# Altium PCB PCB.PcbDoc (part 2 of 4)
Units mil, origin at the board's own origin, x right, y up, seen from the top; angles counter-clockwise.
Board outline 6311.26 x 4737.49 mil, 2 copper layers (Top Layer, Bottom Layer); 252 components, 238 nets, 1140 pads, 635 vias.
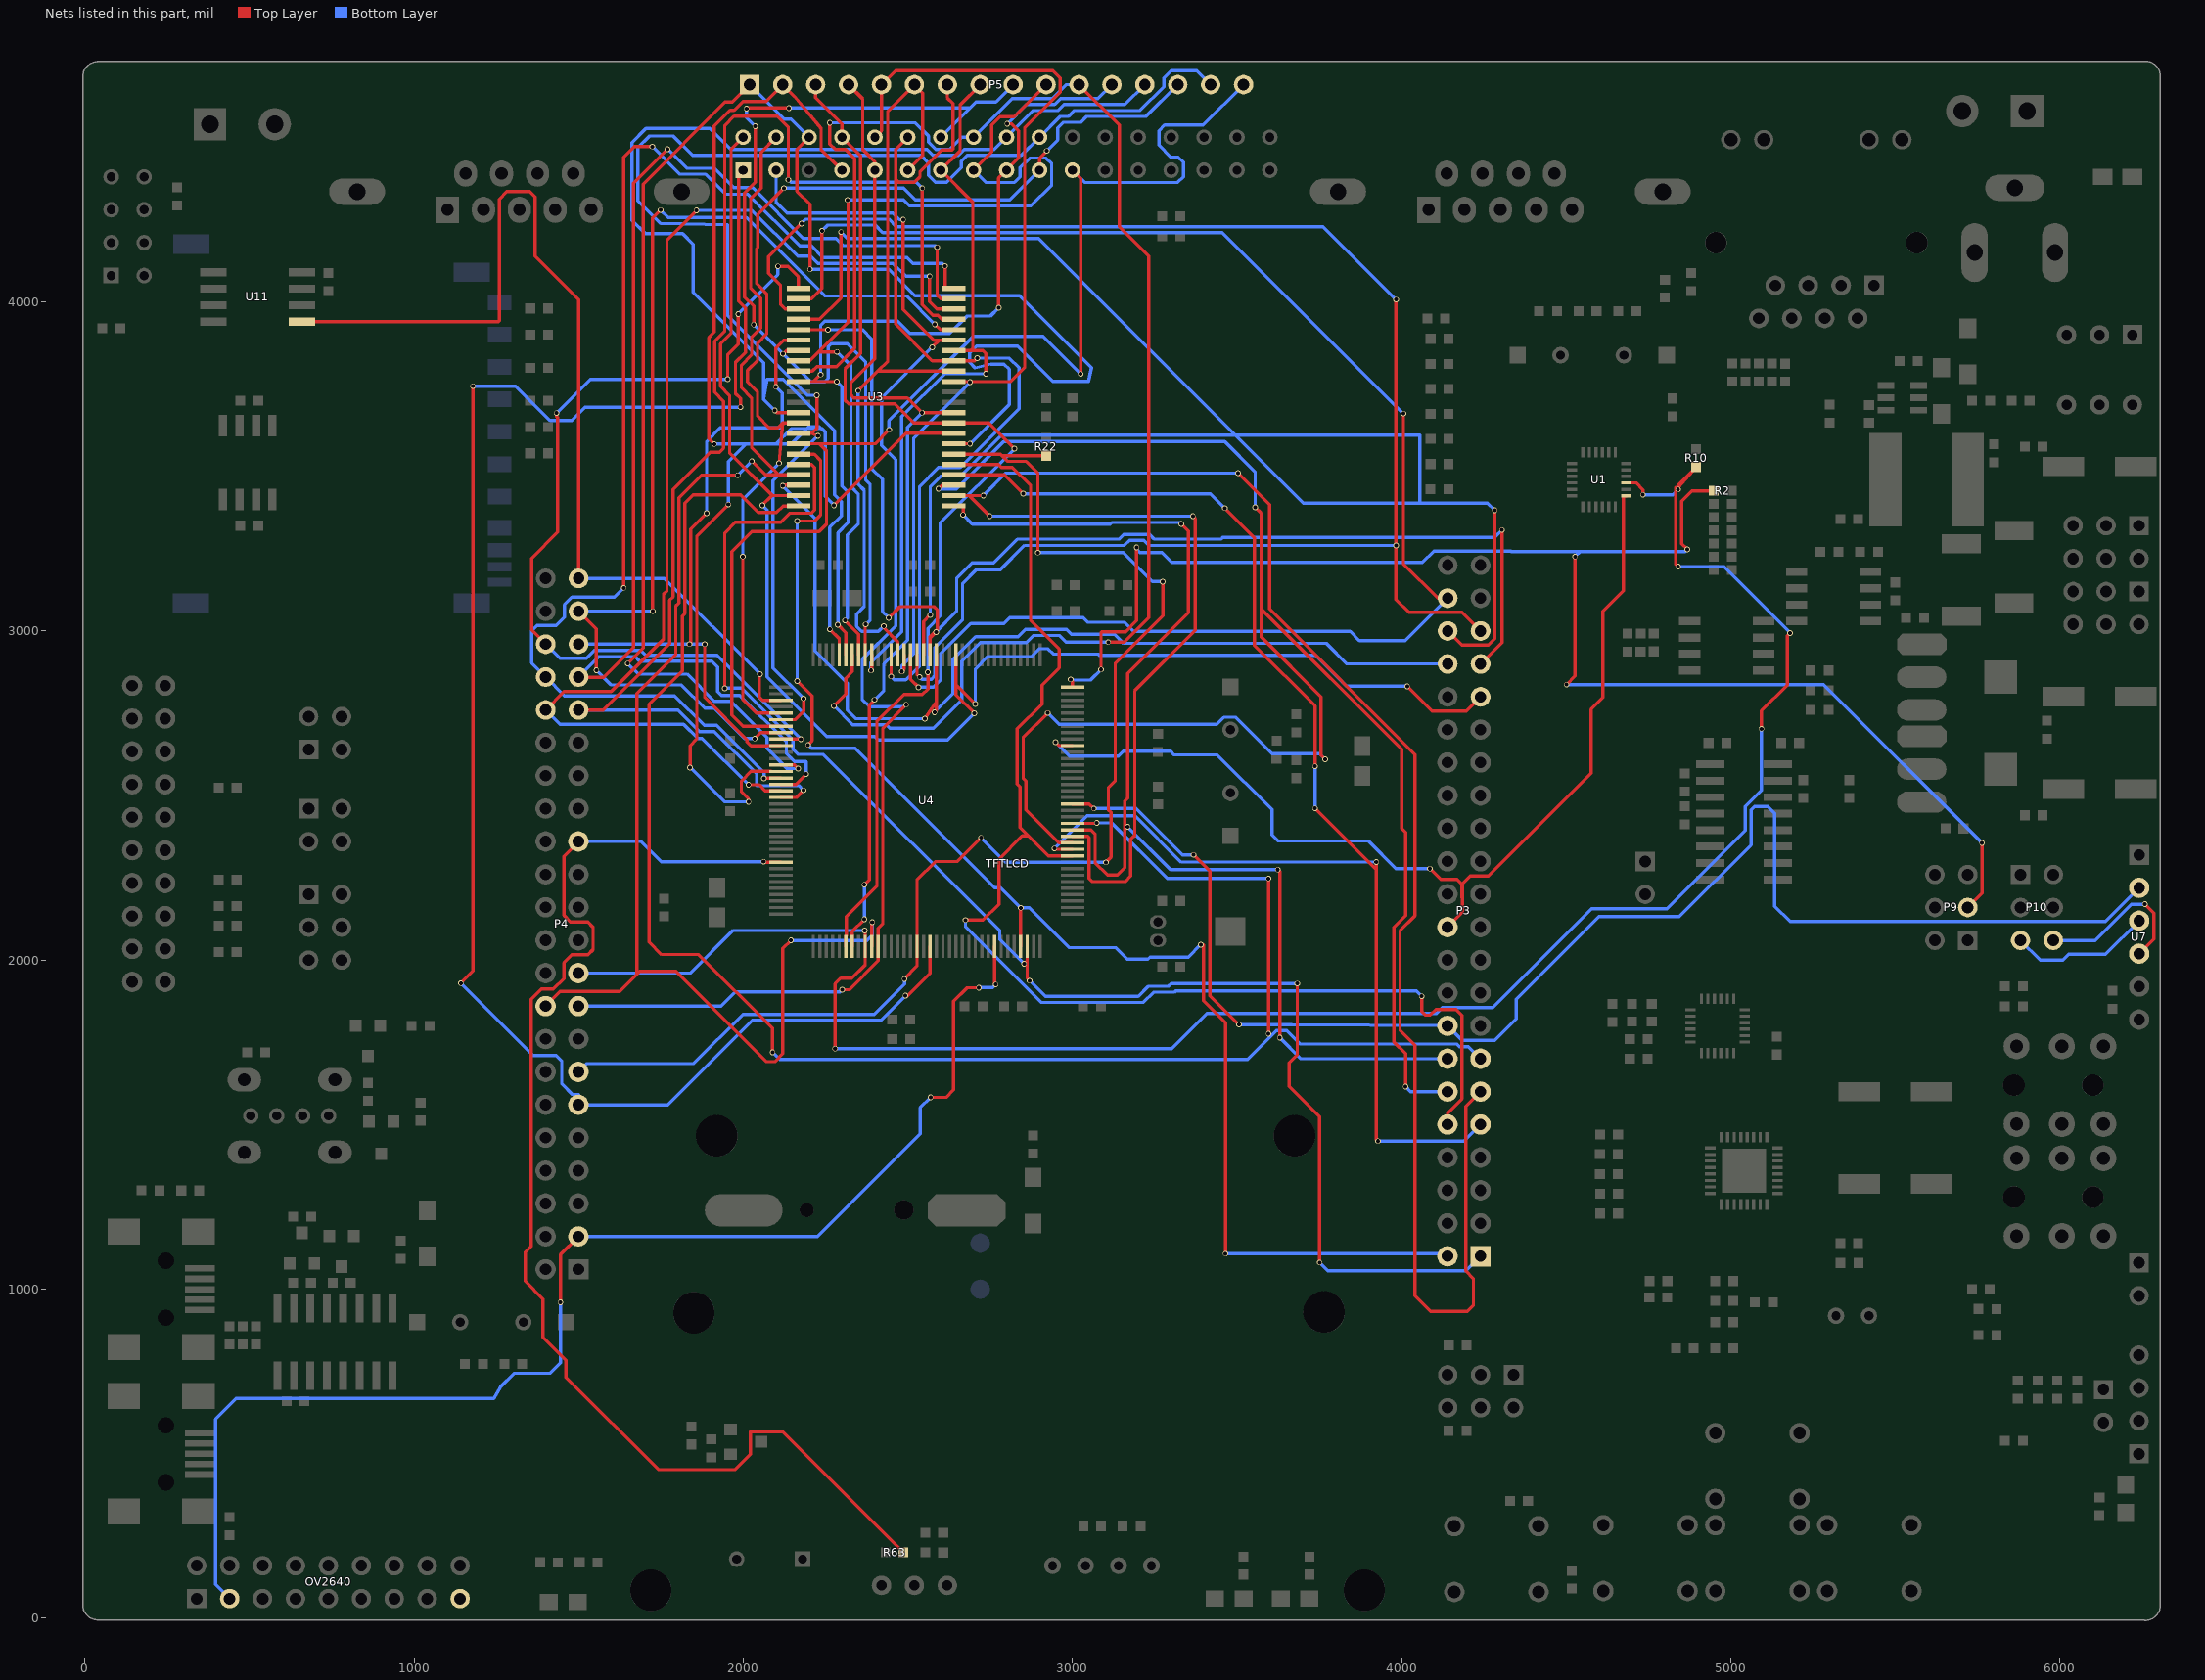
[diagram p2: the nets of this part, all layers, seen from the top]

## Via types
v1: diameter 17, hole 12, Top Layer to Bottom Layer, 622 vias
v2: diameter 25, hole 15, Top Layer to Bottom Layer, 9 vias
v3: diameter 275.59, hole 129.92, Top Layer to Bottom Layer, 4 vias

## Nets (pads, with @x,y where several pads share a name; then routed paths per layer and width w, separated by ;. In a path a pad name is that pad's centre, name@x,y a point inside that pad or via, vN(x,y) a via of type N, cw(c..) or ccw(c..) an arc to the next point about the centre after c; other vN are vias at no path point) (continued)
DCMI_VSYNC: OV2640.3 P4.3 U4.137 | length 3998.9
  Top Layer w10: v1(1445,960) 1445,1105.85 P4.3@1499.58,1160.43 ; v1(2569,1583) 2616,1583 2639,1606 2639,1875 2680,1916 v1(2716,1916) ; U4.137@2764.13,2041.55 2764.13,1928.87 v1(2766.93,1926.07)
  Bottom Layer w10: OV2640.3@440,60 397,103 397,605 460,668 1242,668 1263,703.5 1304,744.5 1412.5,744.5 1445,777 v1(1445,960) ; P4.3@1499.58,1160.43 2226,1160.43 2538,1472.43 2538,1552 v1(2569,1583) ; v1(2716,1916) 2716.5,1916.5 2757.36,1916.5 v1(2766.93,1926.07)
DCMI_XCLK: OV2640.17
DCMI_XLCK: P4.27 R63.1 U4.100 | length 3924
  Top Layer w10: P4.27@1499.58,2360.43 1455,2315.85 1455,2136 1475,2116 1528,2116 1544,2100 1544,2032 1528,2016 1479,2016 1455,1992 1455,1944 1423,1912 1386.5,1912 1355.5,1881 1355.5,1130.92 1337.58,1113 1337.58,1024.42 1392,970 1392,854 1462,784 1462,732 1742,452 1976,452 2022,498 2022,567 2120,567 R63.1@2487,200 ; v1(2062,2299) 2063.54,2297.46 U4.100@2114.53,2297.46
  Bottom Layer w10: P4.27@1499.58,2360.43 1689.74,2360.43 1751.17,2299 v1(2062,2299)
ETH_MDC: P3.22 U1.13 U4.27 | length 3184.7
  Top Layer w9.84: 4674,3121.71 4674,3410.79 U1.13@4682.72,3410.79
  Top Layer w10: v1(2949,2662) 2959.21,2651.79 U4.27@3000.35,2651.79 ; v1(4086,2278) 4119,2245 4168,2245 4183,2230 ; P3.22@4139.58,2100.43 4185,2145.85 ; 4674,3121.71 4611.79,3059.5 4611.79,2797.79 4576,2762 4576,2568 4264,2256 4209,2256 4183,2230 ; 4183,2230 4185,2145.85 ; 4183,2230 4185,2228 4185,2145.85
  Bottom Layer w10: v1(2949,2662) 2991,2620 3140.16,2620 3154.66,2634.5 3298.5,2634.5 3309.5,2623.5 3440.5,2623.5 3606,2458 3606,2380.05 3624,2362.05 3898.55,2362.05 3982.6,2278 v1(4086,2278)
ETH_MDIO: P9.3 R2.1 U4.36 | length 4985.2
  Top Layer w10: v1(2995,2853) 3000.35,2847.65 U4.36@3000.35,2828.95 ; v1(3087,2883) 3087,2996.14 3088.49,2997.64 3161.64,2997.64 3195,3031 v1(3195,3254) ; v1(4501,2837) 4527,2863 v1(4527,3226) ; v1(4868,3248) 4851,3265 4851,3394.87 4882.13,3426 R2.1@4948,3426 ; P9.3@5720,2160 5763,2203 v1(5763,2356)
  Bottom Layer w10: v1(2995,2853) 2995,2851 3055,2851 v1(3087,2883) ; v1(3195,3254) 3195,3248 3205,3238 3272,3238 3302,3208 4063,3208 4098,3243 4331.41,3243 4332.66,3241.75 4542.75,3241.75 ; v1(4501,2837) 5282,2837 v1(5763,2356) ; v1(4527,3226) 4542.75,3241.75 ; v1(4868,3248) 4861.75,3241.75 ; 4542.75,3241.75 4861.75,3241.75 ; 4542.75,3241.75 4861.75,3241.75
ETH_RESET: P4.19 R10.2 U1.15 U4.117 | length 6072.8
  Top Layer w9.84: U1.15@4682.72,3450.16 4712,3450.16 4733,3429.16
  Top Layer w10: v1(2279,1731) 2279,1928 2296,1945 2330,1945 2370.43,1985.43 U4.117@2370.43,2041.55 2370.43,2088.57 v1(2369,2090) ; v1(4733,3414) 4733,3429.16 ; v1(4840,3196) 4833,3203 4833,3430 4833,3436.56 v1@4840,3436.56 ; v1(4840,3430) v1@4840,3436.56 ; v1(5093,2703) 5093,2757.52 5171.5,2836.02 5171.5,2985.5 v1(5180,2994) ; v1@4840,3436.56 R10.2@4894.94,3498.5 4840,3443.56 v1@4840,3436.56
  Bottom Layer w10: P4.19@1499.58,1960.43 1839.56,1960.43 1969.14,2090 v1(2369,2090) ; v1(2279,1731) 2279.5,1730.5 3301.5,1730.5 3409,1838 4106,1838 4124,1856 4277.5,1856 4577.5,2156 4806,2156 5043.5,2393.5 5043.5,2466.26 5093,2515.76 v1(5093,2703) ; v1(4733,3414) 4824,3414 v1(4840,3430) ; v1(4840,3196) 4978,3196 v1(5180,2994)
F_CS: P4.43 U4.75 U11.1 | length 3120.6
  Top Layer w10: U11.1@660,3940 1256,3940 1259,3943 1259,4312 1282,4335 1352,4335 1368,4319 1368,4139 1500,4007 P4.43@1500,3160 ; v1(2051,2869) 2048.09,2866.09 2048.09,2800 2058.51,2789.58 U4.75@2114.53,2789.58
  Bottom Layer w10: P4.43@1500,3160 1760,3160 v1(2051,2869)
FSMC_A0: P3.10 U3.5 U4.10 | length 4107.8
  Top Layer w10: U3.5@2640.35,3505.96 2775,3505.96 2783.96,3497 2817.73,3497 2873,3441.73 2873,3031.73 2959.94,2944.79 2959.94,2888 2907.5,2835.56 2907.5,2777.76 2832.5,2702.76 2832.5,2534.5 2840.82,2526.18 2840.82,2402.94 2866.3,2377.45 ; v1(2675.29,2121.5) 2728.45,2121.5 2776.48,2169.53 2776.48,2306.49 2847.45,2377.45 2866.3,2377.45 ; U4.10@3000.35,2317.14 2926.62,2317.14 ; v1(4061,1890.21) 4061,1843.93 4072,1832.93 4086.93,1832.93 4104,1850 4165.58,1850 4183.58,1832 4183.58,1578.42 4139.58,1534.42 P3.10@4139.58,1500.43 ; 2866.3,2377.45 2926.62,2317.14 ; 2866.3,2377.45 2926.62,2317.14
  Bottom Layer w10: v1(2675.29,2121.5) 2675.29,2101.46 2905.25,1871.5 3215.36,1871.5 3246.36,1902.5 3309.89,1902.5 3313.81,1906.42 4044.79,1906.42 v1(4061,1890.21)
FSMC_A1: P3.9 U3.4 U4.11 | length 5289.7
  Top Layer w10: U3.4@2640.35,3474.46 2793.52,3474.46 v1(2850.84,3417.14) ; v1(2945.17,2339.17) 2947.52,2336.83 U4.11@3000.35,2336.83 ; v1(3462.83,3373.17) 3553.5,3282.5 3553.5,2955.79 3737,2772.29 v1(3737,2589) ; v1(3737,2461) 3923.09,2274.91 ; v1(3923.09,2298) 3923.09,2274.91 ; v1(3928,1450) v1@3923.09,1454.91 ; v1@3923.09,1454.91 3923.09,2274.91 ; v1@3923.09,1454.91 3923.09,2274.91
  Bottom Layer w10: v1(2850.84,3417.14) 3418.86,3417.14 v1(3462.83,3373.17) ; v1(2945.17,2339.17) 3045,2439 3189.63,2439 3330.63,2298 v1(3923.09,2298) ; v1(3737,2461) v1(3737,2589) ; v1(3928,1450) 4189.15,1450 P3.9@4239.58,1500.43
FSMC_A2: P3.12 U3.3 U4.12 | length 5591.6
  Top Layer w10: v1(2593,3432) 2603.97,3442.97 U3.3@2640.35,3442.97 ; v1(2925,2751) 2850.5,2676.5 2850.5,2552.5 2858.82,2544.18 2858.82,2456.64 2958.94,2356.51 U4.12@3000.35,2356.51 ; v1(3555,3376) 3573,3358 ; v1(3768,2610) 3755.5,2622.5 3755.5,2799.5 3573,2982 3573,3067.54 ; v1(4012,1616) 4012,1716.09 3977.09,1751 3977.09,2100.09 4012,2135 4012,2388 4000,2400 4000,2640.54 3573,3067.54 ; 3573,3067.54 3573,3358 ; 3573,3067.54 3573,3358
  Bottom Layer w10: v1(2593,3432) 2647.17,3432 2791.17,3576 3463,3576 3555,3484 v1(3555,3376) ; v1(2925,2751) 2959.5,2716.5 3438.5,2716.5 3460,2738 3496,2738 3607,2627 3751,2627 v1(3768,2610) ; v1(4012,1616) 4027.57,1600.43 P3.12@4139.58,1600.43
FSMC_A3: P3.11 U3.2 U4.13 | length 6776.1
  Top Layer w10: v1(2729.47,3411.47) 2686.53,3411.47 ; v1(2749,3349) 2686.53,3411.47 ; U4.13@3000.35,2376.2 3047,2376.2 3051,2372.2 3051,2248 3060.47,2238.53 3160,2238.53 3176.53,2255.05 3176.53,2366.58 3189.5,2379.56 3189.5,2818.5 3373.33,3002.33 3373.33,3341.67 v1(3366,3349) ; v1(3503,3480) 3599,3384 3599,3067 4041,2625 4041,2134.54 3995.09,2088.64 3995.09,1787.19 4041,1741.28 4041,980 4088,933 4200,933 4218,951 4218,1033 4195,1056 4195,1555.85 P3.11@4239.58,1600.43 ; 2686.53,3411.47 U3.2@2640.35,3411.47 2686.53,3411.47
  Bottom Layer w10: v1(2729.47,3411.47) 2798,3480 v1(3503,3480) ; v1(2749,3349) v1(3366,3349)
FSMC_A4: P3.14 U3.1 U4.14 | length 3829.6
  Top Layer w10: U3.1@2640.35,3379.98 2668,3379.98 v1(2668,3353) ; U4.14@3000.35,2395.88 3057.12,2395.88 3069,2384 3069,2296 3106.74,2258.26 3136.26,2258.26 3158.53,2280.53 ; v1(3168,2405) 3158.53,2395.53 ; v1(3331,3325) 3352,3304 3352,3055.59 3167.5,2871.09 3167.5,2492.5 3158.53,2483.53 3158.53,2405 3158.53,2395.53 ; v1(3624,2275) 3630,2269 v1(3630,1764.43) ; 3158.53,2280.53 3158.53,2395.53 ; 3158.53,2280.53 3158.53,2395.53
  Bottom Layer w10: v1(2668,3353) 2696,3325 3115,3325 3119.5,3329.5 3326.5,3329.5 v1(3331,3325) ; v1(3168,2405) 3298,2275 v1(3624,2275) ; v1(3630,1764.43) 3694,1700.43 P3.14@4139.58,1700.43
FSMC_A5: P3.13 U3.44 U4.15 | length 5724.4
  Top Layer w10: v1(2089,1720) 2089,1793 1865,2017 1752,2017 1714,2055 1714,2777 1815,2878 1815,3045.67 1822.5,3053.17 1822.5,3388.5 1848,3414 1992,3414 2046,3360 2101.02,3360 2121,3379.98 U3.44@2167.91,3379.98 ; U4.15@3000.35,2415.57 3072.57,2415.57 v1(3074,2417) ; v1(3596,1776) v1(3596,2248)
  Bottom Layer w10: v1(2089,1720) 2110.5,1698.5 3532.26,1698.5 3602.88,1769.12 ; v1(3074,2417) 3119,2417 3288,2248 v1(3596,2248) ; v1(3596,1776) 3602.88,1769.12 ; P3.13@4239.58,1700.43 4203.22,1736.78 4176.22,1736.78 4168,1745 3692.43,1745 3651.5,1785.93 3619.69,1785.93 ; 3602.88,1769.12 3619.69,1785.93 ; 3602.88,1769.12 3619.69,1785.93
FSMC_A6: P3.35 TFTLCD.2 U3.43 U4.50 | length 4792
  Top Layer w10: TFTLCD.2@1999.92,4500.24 1963,4463.31 1963,3904.3 1931.09,3872.39 1931.09,3743.5 1958.5,3716.09 1958.5,3541.5 2088.53,3411.47 ; v1(2058,3382) 2087.47,3411.47 2088.53,3411.47 ; v1(2702,2750) 2646.02,2805.98 2646.02,2836.98 ; v1(2705,2778) 2646.02,2836.98 ; v1(4017,2832) 4092,2757 4197,2757 P3.35@4240,2800 ; 2088.53,3411.47 U3.43@2167.91,3411.47 2088.53,3411.47 ; 2646.02,2836.98 U4.50@2646.02,2927.38 2646.02,2836.98
  Bottom Layer w10: v1(2058,3382) 2072.5,3367.5 2072.5,2860.56 2253.56,2679.5 2399.36,2679.5 2410.37,2668.5 2620.5,2668.5 v1(2702,2750) ; v1(2705,2778) 2705,2885 2742,2922 2875,2922 2899,2946 2926,2946 2942,2930 3078.5,2930 3082,2926.5 3738.5,2926.5 3833,2832 v1(4017,2832)
FSMC_A7: P3.38 U3.42 U4.53 | length 3206.5
  Top Layer w10: v1(2120,3441) 2121.97,3442.97 U3.42@2167.91,3442.97 ; v1(2551.5,2733.5) 2570.11,2760.5 2586.97,2784.97 ; v1(2581,2753) 2586.97,2758.97 2586.97,2784.97 ; 2586.97,2784.97 U4.53@2586.97,2927.38 2586.97,2784.97
  Bottom Layer w10: v1(2120,3441) 2218,3343 2218,2939 2316,2841 2316,2760 2342.5,2733.5 v1(2551.5,2733.5) ; v1(2581,2753) 2636.5,2808.5 2636.5,2912.47 2706.26,2982.23 2835.23,2982.23 2857.5,3004.5 2982.5,3004.5 2996.5,2990.5 3127.14,2990.5 3155.14,2962.5 3771.77,2962.5 3834.27,2900 P3.38@4140,2900
FSMC_A8: P3.37 U3.27 U4.54 | length 3843.9
  Top Layer w10: U3.27@2167.91,3915.41 v1(2257.41,3915.41) ; v1(2442,3040) 2476,3074 2579.5,3074 2589.5,3064 2589.5,3004.5 2584,2999 2567.28,2982.28 2567.28,2978.28 ; v1(2586,2997) 2567.28,2978.28 ; P3.37@4240,2900 4305,2965 v1(4305,3307) ; 2567.28,2978.28 U4.54@2567.28,2927.38 2567.28,2978.28
  Bottom Layer w10: v1(2257.41,3915.41) 2362.13,3915.41 2391,3886.54 2391,3493 2423,3461 2423,3059 v1(2442,3040) ; v1(2586,2997) 2648.39,3059.39 2648.39,3160 2695.8,3207.41 2761.13,3207.41 2832.72,3279 3141,3279 3155.5,3293.5 3234.5,3293.5 3249,3279 3451.25,3279 3456.35,3284.1 4282.1,3284.1 v1(4305,3307)
FSMC_A9: P3.40 U3.26 U4.55 | length 5735
  Top Layer w10: U3.26@2167.91,3946.91 2232.01,3946.91 2297,4011.9 v1(2297,4212) ; U4.55@2547.6,2927.38 2547.6,3028.38 v1(2568,3048.78) ; P3.40@4140,3000 4183,2957 4264,2957 4283,2976 v1(4283,3367)
  Bottom Layer w10: v1(2297,4212) 2316.5,4192.5 2897.5,4192.5 3495,3595 ; v1(2568,3048.78) 2568,3437.5 2601.54,3471.04 2660.76,3471.04 2784.71,3595 3495,3595 ; v1(4283,3367) 4261.17,3388.83 ; 3495,3595 3701.17,3388.83 4055,3388.83 ; 3495,3595 4055,3595 4055,3388.83 ; 4055,3388.83 4261.17,3388.83 ; 4055,3388.83 4261.17,3388.83
FSMC_A10: P3.39 U3.25 U4.56 | length 5464
  Top Layer w10: U3.25@2167.91,3978.4 2127,3978.4 2113.41,3992 2113.41,4049.59 2076.5,4086.5 2076.5,4137.5 v1(2177,4238) ; U4.56@2527.91,2927.38 2527.91,2868.5 v1(2536,2860.41) ; v1(3983,4007) v1(3983,3260) ; P3.39@4240,3000 4183,3057 4022,3057 3983,3096 ; 3983,3096 v1(3983,3260) ; 3983,3096 v1(3983,3260)
  Bottom Layer w10: v1(2177,4238) 2190.5,4251.5 2441.88,4251.5 2464.88,4228.5 3761.5,4228.5 v1(3983,4007) ; v1(2536,2860.41) 2542.91,2853.5 2571.5,2853.5 2582.5,2864.5 2582.5,2950.13 2666.39,3034.02 2666.39,3144.53 2707.35,3185.5 2780.5,3185.5 2855,3260 3158,3260 3173.5,3275.5 3216.5,3275.5 3232,3260 v1(3983,3260)
FSMC_A11: P3.42 U3.24 U4.57 | length 4837.1
  Top Layer w10: U3.24@2167.91,4009.9 2208,4009.9 2239,4040.9 v1(2239,4216) ; U4.57@2508.23,2927.38 2508.23,2853.27 v1(2532.5,2829) ; v1(4005.5,3660.5) 4005.5,3204.43 4109.93,3100 P3.42@4140,3100
  Bottom Layer w10: v1(2239,4216) 2256.5,4233.5 2400.88,4233.5 2423.88,4210.5 3455.5,4210.5 v1(4005.5,3660.5) ; v1(2532.5,2829) 2577.5,2829 2600.5,2852 2600.5,2932.13 2691.36,3022.99 2791.99,3022.99 2809.5,3040.5 3032.5,3040.5 3046.5,3026.5 3157.36,3026.5 3185.36,2998.5 3843.68,2998.5 3871.68,2970.5 4010.5,2970.5 P3.42@4140,3100
FSMC_A12: P4.38 U3.22 U4.87 | length 3911.1
  Top Layer w10: v1(1637.25,3131) 1637.25,4440 1669.25,4472 v1(1724,4472) ; v1(2063,2552) 2064.36,2553.36 U4.87@2114.53,2553.36 ; v1(2613,4109) 2613,4041.39 U3.22@2640.35,4041.39
  Bottom Layer w10: v1(1637.25,3131) 1609.25,3103 1480,3103 1457,3080 1457,3042 1432,3017 1374,3017 1357,3000 1357,2903 P4.38@1400,2860 1457,2803 1792,2803 1882,2713 1919.99,2713 2063,2569.99 v1(2063,2552) ; v1(1724,4472) 1808,4388 1886,4388 1947,4327 2015,4327 2172,4170 2207.27,4170 2242.27,4135 2497.18,4135 2514.92,4117.27 2604.73,4117.27 v1(2613,4109)
FSMC_A13: P4.37 U3.21 U4.88 | length 3945.8
  Top Layer w10: P4.37@1500,2860 1501,2859 1576,2859 1667,2950 1667,4361 v1(1770,4464) ; U4.88@2114.53,2533.68 2159.68,2533.68 v1(2191,2565) ; v1(2589,4166) 2589,4020.9 2600,4009.9 U3.21@2640.35,4009.9
  Bottom Layer w10: P4.37@1500,2860 1562.5,2922.5 1670.5,2922.5 1685.2,2907.8 1904.7,2907.8 1922.5,2890 1922.5,2816 1934,2804.5 1989.47,2804.5 2131.22,2662.75 2131.22,2627.69 2155.31,2603.61 2190.37,2603.61 2191,2602.97 v1(2191,2565) ; v1(1770,4464) 1828,4406 1912,4406 1971,4347 2029,4347 2183,4193 2282,4193 2304,4171 2584,4171 v1(2589,4166)
FSMC_A14: P4.36 U3.20 U4.89 | length 3559.5
  Top Layer w10: P4.36@1400,2760 1456,2816 1599,2816 1758,2975 1758,3112 1768.5,3122.5 1768.5,4188.5 v1(1858,4278) ; v1(2016,2533) 2048,2533 2067.01,2513.99 U4.89@2114.53,2513.99 ; v1(2566,4078) 2566,4001 2588.6,3978.4 U3.20@2640.35,3978.4
  Bottom Layer w10: P4.36@1400,2760 1443,2717 1819,2717 1862.19,2673.81 1875.19,2673.81 v1(2016,2533) ; v1(1858,4278) 2027,4278 2166,4139 2205,4139 2227,4117 2455,4117 2494,4078 v1(2566,4078)
FSMC_A15: P4.35 U3.19 U4.90 | length 4189.5
  Top Layer w10: P4.35@1500,2760 1574.5,2760 1776.31,2961.81 1776.31,3093.5 1786.5,3103.69 1786.5,3429.5 1900,3543 1928,3543 1940.5,3555.5 1940.5,3698.09 1913.09,3725.5 1913.09,3881.09 1944,3912 1944,4536 1972,4564 2104,4564 2137,4531 v1(2137,4371) ; U4.90@2114.53,2494.31 2161.31,2494.31 v1(2183,2516) ; v1(2544,4345.61) 2544,3992 2576.66,3959.34 2591.06,3959.34 2603.5,3946.91 U3.19@2640.35,3946.91
  Bottom Layer w10: P4.35@1500,2760 1801.46,2760 1866.85,2694.61 1912.21,2694.61 2041.09,2565.72 2041.09,2530.04 2168.96,2530.04 v1(2183,2516) ; v1(2137,4371) 2144.62,4363.38 2526.24,4363.38 v1(2544,4345.61)
FSMC_A16: P4.41 U3.18 U4.80 | length 3351.5
  Top Layer w10: P4.41@1500,3060 1554,3006 v1(1554,2881) ; v1(1725,3060) 1725,4255 v1(1749,4279) ; v1(2035,2673) 2053.16,2691.16 U4.80@2114.53,2691.16 ; v1(2582,3931.41) 2598,3915.41 U3.18@2640.35,3915.41
  Bottom Layer w10: P4.41@1500,3060 v1(1725,3060) ; v1(1554,2881) 1599,2836 1812.73,2836 1883.36,2765.36 1911.99,2765.36 2004.35,2673 v1(2035,2673) ; v1(1749,4279) 1771.5,4256.5 2009.38,4256.5 2247.89,4017.99 2495.42,4017.99 v1(2582,3931.41)
FSMC_A17: P4.40 U3.23 U4.81 | length 2807.4
  Top Layer w10: P4.40@1400,2960 1357,3003 1357,3221 1436,3300 1436,3648 1433,3651 v1(1433,3662) ; v1(1952.59,3765) 1952.59,3838.99 1985,3871.39 v1(1985,3963) ; v1(2105.28,4108) 2136,4108 2168,4076 2168,4041.39 U3.23@2167.91,4041.39 ; U4.81@2114.53,2671.47 v1(2175,2671.47)
  Bottom Layer w10: P4.40@1400,2960 1443,2917 1523.84,2917 1547.34,2940.5 1688.5,2940.5 1703.2,2925.8 1920.68,2925.8 v1(2175,2671.47) ; v1(1433,3662) 1536,3765 v1(1952.59,3765) ; v1(1985,3963) 2105.28,4083.28 v1(2105.28,4108)
FSMC_A18: P4.39 U3.28 U4.82 | length 2391.5
  Top Layer w10: v1(1837,2960) 1840.5,2963.5 1840.5,3309.5 v1(1889,3358) ; v1(1883,2960) 1883,2798 2011.61,2669.39 2011.61,2663.39 2024,2651 2072.13,2651 2072.91,2651.79 U4.82@2114.53,2651.79 ; v1(2099,3742) 2099,3860 2122.91,3883.91 U3.28@2167.91,3883.91
  Bottom Layer w10: v1(1883,2960) v1(1837,2960) ; v1(1889,3358) 1889,3576 1930,3617 2118,3617 2118,3723 v1(2099,3742) ; v1(1837,2960) P4.39@1500,2960 v1(1837,2960)
FSMC_D0: P5.1 TFTLCD.6 U3.7 U4.85 | length 5254
  Top Layer w10: v1(1649,2901) 1696.18,2948.18 1696.18,4358.18 1945,4607 1967,4607 P5.1@2020,4660 ; U4.85@2114.53,2592.73 2156.27,2592.73 v1(2167,2582) ; TFTLCD.6@2199.92,4500.24 2163,4463.31 2163,4336 2203,4296 v1(2203,4099) ; U3.7@2640.35,3568.95 v1(2689,3568.95)
  Bottom Layer w10: v1(1649,2901) 1681,2869 1829.5,2869 1912,2786.5 1962.5,2786.5 2072.09,2676.91 2072.09,2643.75 2133.84,2582 v1(2167,2582) ; P5.1@2020,4660 2125.14,4554.86 2145.3,4554.86 TFTLCD.6@2199.92,4500.24 ; v1(2203,4099) 2442,4099 2522,4019 2839,4019 3058,3800 3049,3759 2940,3759 2833,3866 2708.97,3866 2688,3845.03 2688,3816 2704.58,3799.42 2752.58,3811 2792,3811 2808,3795 2808,3687.95 v1(2689,3568.95)
FSMC_D1: P5.2 TFTLCD.7 U3.8 U4.86 | length 4472.8
  Top Layer w10: v1(1838.5,2585) 1838.5,2651.5 1859,2672 1859,3288 v1(1955,3384) ; v1(1912,3568) 1895.09,3584.91 1895.09,3891.59 1912,3908.5 1912,4534 1960,4582 1972.26,4582 1999.26,4609 2069,4609 P5.2@2120,4660 2155.75,4624.25 2236.54,4526.92 2236.54,4463.46 TFTLCD.7@2300,4400 ; v1(2016,2481) 2016,2490 1994.5,2511.5 1994.5,2544 2024,2573.5 2084.05,2573.5 2084.5,2573.05 U4.86@2114.53,2573.05 ; v1(2276,3382) 2494.45,3600.45 U3.8@2640.35,3600.45
  Bottom Layer w10: v1(1838.5,2585) 1942.5,2481 v1(2016,2481) ; v1(1912,3568) 2008,3568 ; v1(1955,3384) 1955,3515 2008,3568 ; v1(2276,3382) 2249,3409 ; 2008,3568 2099,3568 ; 2099,3568 2146,3615 2193,3615 ; 2099,3568 2146,3568 2193,3615 ; 2193,3615 2238,3615 ; 2193,3615 2199,3621 2232,3621 2238,3615 ; 2238,3615 2249,3604 ; 2238,3615 2240,3615 2249,3606 2249,3604 ; 2249,3409 2249,3604 ; 2249,3409 2249,3604
FSMC_D2: P5.3 TFTLCD.8 U3.9 U4.114 | length 3368
  Top Layer w10: P5.3@2220,4660 2220,4621.06 2300,4541.06 TFTLCD.8@2300,4500 2356.47,4443.53 2356.47,3843.47 2309.5,3796.5 2309.5,3701 2320.05,3690.45 2460.14,3690.45 2518.64,3631.95 U3.9@2640.35,3631.95 2746.05,3631.95 v1(2824,3554) ; U4.114@2311.38,2041.55 2311.38,2072.48 2312.85,2073.95 2312.85,2131.77 2406.03,2224.95 2406.03,2725.03 2488,2807 2544,2807 2561,2824 v1(2561,2875)
  Bottom Layer w10: v1(2561,2875) 2561,3008 2599,3046 2599,3329 v1(2824,3554)
FSMC_D3: P5.4 TFTLCD.9 U3.10 U4.115 | length 3051
  Top Layer w10: P5.4@2320,4660 2363,4617 2363,4463 2399.92,4426.08 TFTLCD.9@2399.92,4400.24 2399.92,3827.39 2327.5,3754.96 2327.5,3717 2336,3708.5 2498.38,3708.5 v1(2543.44,3663.44) U3.10@2640.35,3663.44 ; U4.115@2331.06,2041.55 2331.06,2087.06 v1(2368,2124) ; v1(2368,2229) 2383,2244 2383,2775 v1(2399,2791)
  Bottom Layer w10: v1(2368,2124) v1(2368,2229) ; v1(2399,2791) 2427,2819 2427,2900.17 2499.5,2972.67 2499.5,3619.5 v1(2543.44,3663.44)
FSMC_D4: P5.5 TFTLCD.10 U3.13 U4.58 | length 2915.6
  Top Layer w10: TFTLCD.10@2399.92,4500.24 2420,4520.31 P5.5@2420,4660 2463,4703 2940,4703 2963,4680 2963,4637 2855,4529 2855,3800 2812.93,3757.93 2689,3757.93 v1@2687.07,3757.93 ; v1(2482,2877.09) 2488.54,2883.63 U4.58@2488.54,2927.38 ; U3.13@2640.35,3757.93 v1@2687.07,3757.93 ; v1(2689,3756) v1@2687.07,3757.93
  Bottom Layer w10: v1(2482,2877.09) 2482,2895 2517.5,2930.5 2517.5,3584.5 v1(2689,3756)
FSMC_D5: P5.6 TFTLCD.11 U3.14 U4.59 | length 2540.2
  Top Layer w10: v1(2427.09,3015) 2427.09,3008.77 2468.86,2967 U4.59@2468.86,2927.38 ; TFTLCD.11@2499.92,4400.24 2545.3,4445.61 2545.3,4634.7 P5.6@2520,4660 2439,4579 2439,3820 2408.43,3789.43 ; U3.14@2640.35,3789.43 2408.43,3789.43 ; 2408.43,3789.43 v1(2349,3730) 2408.43,3789.43
  Bottom Layer w10: v1(2349,3730) 2349,3446.27 2367.5,3427.77 2367.5,3074.5 2344,3051 2344,3014.5 2360,2998.5 2410.59,2998.5 v1(2427.09,3015)
FSMC_D6: P5.7 TFTLCD.12 U3.15 U4.60 | length 2784.9
  Top Layer w10: v1(2449.17,2862) U4.60@2449.17,2927.38 ; TFTLCD.12@2499.92,4500.24 2463,4463.31 ; P5.7@2620,4660 2620,4620 2637,4603 2637,4464 2635,4462 2603,4462 2537,4396 2537,4380.61 2520,4363.61 2472,4363.61 2463,4372.61 ; v1(2711,3829) 2702.92,3820.92 U3.15@2640.35,3820.92 2574,3820.92 2463,3931.92 2463,4372.61 ; 2463,4372.61 2463,4463.31 ; 2463,4372.61 2463,4463.31
  Bottom Layer w10: v1(2449.17,2862) 2459.17,2852 2494,2852 2535.5,2893.5 2535.5,3439 2592.91,3496.41 2658.95,3496.41 2837.58,3675.04 2837.58,3800 2808.58,3829 v1(2711,3829)
FSMC_D7: P5.8 TFTLCD.13 U3.16 U4.63 | length 2281.5
  Top Layer w10: v1(2388,2880) 2390.12,2882.12 U4.63@2390.12,2927.38 ; P5.8@2720,4660 2658.84,4598.84 2658.84,4459.16 TFTLCD.13@2599.92,4400.24 2697.5,4302.66 2697.5,3858.42 2691.5,3852.42 ; v1(2737,3781.42) 2737,3843.41 2728,3852.42 2691.5,3852.42 ; 2691.5,3852.42 U3.16@2640.35,3852.42 2691.5,3852.42
  Bottom Layer w10: v1(2388,2880) 2388,2904.23 2481.5,2997.73 2481.5,3651.5 2611.42,3781.42 v1(2737,3781.42)
FSMC_D8: P5.9 TFTLCD.14 U3.29 U4.64 | length 3175.8
  Top Layer w10: v1(2010,4587) 2012,4589 v1(2139,4589) ; v1(2032,3931) 2032,3987.24 2004.5,4014.74 2004.5,4331.5 2036.54,4363.54 v1(2036.54,4533.54) ; v1(2121,3842) 2131.42,3852.42 U3.29@2167.91,3852.42 ; U4.64@2370.43,2927.38 2370.43,3018.43 v1(2372,3020)
  Bottom Layer w10: v1(2010,4587) 2010,4560.09 v1(2036.54,4533.54) ; v1(2032,3931) v1(2121,3842) 2206,3757 2247.5,3757 2258.5,3768 2258.5,3864 2267.63,3873.13 2315.87,3873.13 2372,3817 2372,3458.27 2385.5,3444.77 2385.5,3033.5 v1(2372,3020) ; v1(2139,4589) 2688.69,4589 ; TFTLCD.14@2599.92,4500.24 2688.69,4589 ; P5.9@2820,4660 2767.42,4607.42 2707.1,4607.42 ; 2688.69,4589 2707.1,4607.42 ; 2688.69,4589 2707.1,4607.42
FSMC_D9: P5.10 TFTLCD.15 U3.30 U4.65 | length 3048.4
  Top Layer w10: U3.30@2167.91,3820.92 U3.30@2201.92,3820.92 ; v1(2285,3848) 2229,3848 ; v1(2309,3032) 2350.75,2990.25 U4.65@2350.75,2927.38 ; v1(2316.97,4309.61) 2319,4307.58 2319,3938 2229,3848 ; TFTLCD.15@2699.92,4400.24 2755,4455.31 2755,4537.02 2780.48,4562.5 2822.5,4562.5 P5.10@2920,4660 ; U3.30@2201.92,3820.92 2229,3848 ; U3.30@2201.92,3820.92 2229,3848
  Bottom Layer w10: v1(2285,3848) 2327.33,3805.67 2327.33,3439.5 2349.5,3417.33 2349.5,3324.5 2316.5,3291.5 2316.5,3039.5 v1(2309,3032) ; v1(2316.97,4309.61) 2486.76,4309.61 2504.5,4291.88 2873.88,4291.88 2937,4355 2937,4420 2920,4437 2870,4437 2841,4408 2841,4380 2824,4363 2737.16,4363 TFTLCD.15@2699.92,4400.24
FSMC_D10: P5.11 TFTLCD.16 U3.31 U4.66 | length 4911.8
  Top Layer w10: U3.31@2167.91,3789.43 2209.93,3789.43 2224,3803.5 2283.07,3803.5 2338.47,3858.89 2338.47,4435.53 2311,4463 2280,4463 2263,4480 v1(2263,4544) ; v1(2275.5,2772.39) 2311.5,2808.39 2311.5,2856.78 2331.06,2876.34 U4.66@2331.06,2927.38 ; P5.11@3020,4660 3143,4537 3143,4228.91 3232.41,4139.5 3232.41,3041.1 3157.31,2966 v1(3108.58,2966)
  Bottom Layer w10: v1(2263,4544) 2523,4544 2563,4504 2563,4485.37 2584.75,4463.61 2627,4463.61 2663.62,4500.24 TFTLCD.16@2699.92,4500.24 2817.16,4617.47 2938.47,4617.47 2981,4660 P5.11@3020,4660 ; v1(2275.5,2772.39) 2332.39,2715.5 2434.5,2715.5 2445.5,2704.5 2578.05,2704.5 2664,2790.44 2664,2908.36 2719.86,2964.23 2859.73,2964.23 2882,2986.5 2960,2986.5 2980.5,2966 v1(3108.58,2966)
FSMC_D11: P5.12 TFTLCD.17 U3.32 U4.67 | length 2777.2
  Top Layer w10: v1(2235,3779) 2213.93,3757.93 ; v1(2284,3757.93) 2213.93,3757.93 ; v1(2287.5,3019) 2311.38,2995.12 U4.67@2311.38,2927.38 ; v1(2776,3982) 2776,4376.31 TFTLCD.17@2799.92,4400.24 2837,4437.31 2837,4520 2816,4541 v1(2802,4541) ; 2213.93,3757.93 U3.32@2167.91,3757.93 2213.93,3757.93
  Bottom Layer w10: v1(2235,3779) 2235,3928 2248,3941 2470,3941 2507,3904 2627,3904 2680,3957 2751,3957 v1(2776,3982) ; v1(2284,3757.93) 2300,3741.93 2300,3440.5 2319,3421.5 2319,3330 2287.5,3298.5 v1(2287.5,3019) ; v1(2802,4541) 2860.47,4599.47 2945.93,4599.47 2963.93,4617.47 3077.47,4617.47 P5.12@3120,4660
FSMC_D12: P5.13 TFTLCD.18 U3.35 U4.68 | length 3930.2
  Top Layer w10: v1(2096,3670) 2102.56,3663.44 U3.35@2167.91,3663.44 ; v1(2263,3005) 2291.69,2976.31 U4.68@2291.69,2927.38
  Bottom Layer w10: v1(2263,3005) 2263,3315 2298,3350 2298,3393 2278,3413 2278,3608 2121,3765 2072,3765 2062,3707.38 ; P5.13@3220,4660 3159.47,4599.47 2974.9,4599.47 2956.9,4581.47 2881.16,4581.47 TFTLCD.18@2799.92,4500.24 2762.69,4463 2672,4463 2654,4445 2576,4445 2558,4463 1963,4463 1899,4527 1704.5,4527 1662,4484.5 1662,4248 1703,4207 1816,4207 1848,4175 1848,4029 2062,3815 2062,3707.38 ; 2062,3704 2062,3707.38 ; 2062,3704 2061.5,3704.5 2062,3707.38 ; 2062,3704 v1(2096,3670) 2062,3704
FSMC_D13: P5.14 TFTLCD.19 U3.36 U4.77 | length 3340.6
  Top Layer w10: v1(1999,3226) 1999,2791.21 2040,2750.21 U4.77@2114.53,2750.21 ; v1(2109,3510) 2120,3631.95 ; v1(2123.72,4345.38) 2044,4265.66 2044,4165.5 2040.5,4162 2040.5,4056 2071.5,4025 2071.5,3902.5 2043.5,3874.5 2043.5,3823 2012.5,3792 2012.5,3757.5 2043.5,3726.5 2043.5,3653 2079,3617.5 2105.55,3617.5 2120,3631.95 ; U3.36@2167.91,3631.95 2120,3631.95 ; TFTLCD.19@2899.92,4400.24 2899.92,4436.92 v1(2922,4459)
  Bottom Layer w10: v1(1999,3226) 1999,3400 v1(2109,3510) ; v1(2123.72,4345.38) 2487,4345.38 2522.5,4309.88 2809.56,4309.88 TFTLCD.19@2899.92,4400.24 ; v1(2922,4459) 2955,4492 2955,4529 2971.47,4545.47 3024.94,4545.47 3042.94,4563.47 3223.47,4563.47 P5.14@3320,4660
FSMC_D14: P5.15 TFTLCD.20 U3.37 U4.78 | length 4321.7
  Top Layer w10: U4.78@2114.53,2730.53 2157.53,2730.53 2183.44,2756.44 v1(2183.44,2795) ; U3.37@2167.91,3600.45 2208,3600.45 ; v1(2223.5,3716) 2223.5,3615.95 2208,3600.45 ; v1(2227,3593) 2208,3600.45
  Bottom Layer w10: v1(2183.44,2795) 2090.57,2887.87 2090.57,3456.57 v1(2227,3593) ; v1(2223.5,3716) 2195.46,3716 1952.02,3959.43 1952.02,4233.98 1749,4238.5 1680.5,4307 1680.5,4468.75 1715.75,4504 1787,4504 1846,4445 2539.89,4445 2563.3,4421.59 2563.3,4384.31 2584,4363.61 2618.61,4363.61 2663,4408 2663,4428 2680,4445 2844.69,4445 TFTLCD.20@2899.92,4500.24 2963.16,4563.47 2987.4,4563.47 3005.4,4581.47 3205.82,4581.47 3277.47,4653.12 3277.47,4680 3300,4702.53 3377.47,4702.53 P5.15@3420,4660
FSMC_D15: P5.16 TFTLCD.21 U3.38 U4.79 | length 3842.6
  Top Layer w10: U4.79@2114.53,2710.84 1999,2710.84 1965.5,2744.34 1965.5,3241 2026.34,3301.84 2230.73,3301.84 2253,3324.11 2253,3547.95 2232,3568.95 ; v1(2443,3611) 2400.95,3568.95 2232,3568.95 ; TFTLCD.21@2999.92,4400.24 3025,4375.16 v1(3025,3781) ; 2232,3568.95 U3.38@2167.91,3568.95 2232,3568.95
  Bottom Layer w10: v1(2443,3611) 2443,3639 2699,3895 2911,3895 v1(3025,3781) ; TFTLCD.21@2999.92,4400.24 3037.16,4363 3320,4363 3337,4380 3337,4424 3321,4440 3299,4440 3263,4476 3263,4520 3280,4537 3397,4537 P5.16@3520,4660
FSMC_NBL0: P3.2 U3.39 U4.141 | length 4275.1
  Top Layer w10: v1(2164,2848) 2209.56,2802.44 2209.56,2666.6 v1(2196.96,2654) ; v1(2164,3334) 2217,3334 2235,3352 2235,3518.46 2216,3537.46 U3.39@2167.91,3537.46 ; U4.141@2842.87,2041.55 v1(2842.87,2158.83) ; v1(3390,2047) 3398.12,2047 3398.12,1876.72 3465,1809.84 v1(3465,1108)
  Bottom Layer w10: v1(2164,2848) v1(2164,3334) ; v1(2196.96,2654) 2207.46,2643.5 2339.67,2643.5 2763.4,2219.77 2781.94,2219.77 v1(2842.87,2158.83) 2869.17,2158.83 2990,2038 3131,2038 3166.5,2002.5 3229.5,2002.5 3236,2009 3352,2009 v1(3390,2047) ; v1(3465,1108) 4132,1108 P3.2@4139.58,1100.43
FSMC_NBL1: P3.1 U3.40 U4.142 | length 4671.6
  Top Layer w10: v1(1944,2826) 1944,3298 1976,3330 2114,3330 2142,3358 2208,3358 2217,3367 2217,3496.96 2208,3505.96 U3.40@2167.91,3505.96 ; v1(2853,1989) 2862.56,1998.56 ; v1(2870,1937.44) 2862.56,1944.88 2862.56,1989 2862.56,1998.56 ; v1(3683,1929) 3683,1712 3658.5,1687.5 3658.5,1617 3751,1524.5 v1(3751,1081) ; 2862.56,1998.56 U4.142@2862.56,2041.55 2862.56,1998.56
  Bottom Layer w10: v1(1944,2826) 1995.02,2826 2151.65,2669.37 2151.65,2640.35 2167,2625 2244,2625 2779.31,2089.69 2779.31,2062.69 v1(2853,1989) ; v1(2870,1937.44) 2917.94,1889.5 3200,1889.5 3231,1920.5 3291.89,1920.5 3300.39,1929 v1(3683,1929) ; v1(3751,1081) 3776,1056 4195.15,1056 P3.1@4239.58,1100.43
FSMC_NE3: P4.13 R22.2 U3.6 U4.125 | length 4099
  Top Layer w10: v1(2490,1943) 2490,1944.09 2527.91,1982 U4.125@2527.91,2041.55 2527.91,2243.58 2583.72,2299.39 2649.59,2299.39 v1(2722.2,2372) ; U3.6@2640.35,3537.46 2781.54,3537.46 ; v1(2895,3238) 2895,3480 2859.59,3515.41 2803.59,3515.41 2786.5,3532.5 ; R22.2@2919.94,3532.5 2786.5,3532.5 ; v1(3101.81,2297.25) 3117.5,2312.94 3117.5,2448.5 3109.14,2456.86 3109.14,2523.5 3129.99,2544.35 3129.99,2901.49 3274.52,3046.02 v1(3274.52,3150.08) ; 2781.54,3537.46 2786.5,3532.5 ; 2781.54,3537.46 2786.5,3532.5
  Bottom Layer w10: P4.13@1499.58,1660.43 1524.87,1685.72 1849.95,1685.72 1999.74,1835.5 2398,1835.5 2490,1927.5 v1(2490,1943) ; v1(2722.2,2372) 2796.94,2297.25 v1(3101.81,2297.25) ; v1(2895,3238) 3154.92,3238 3242.84,3150.08 v1(3274.52,3150.08)
FSMC_NE4: P4.11 TFTLCD.1 U4.127 | length 5340
  Top Layer w10: v1(1142,1930) 1179,1967 v1(1179,3744) ; v1(1991.95,3680) 1991.95,3706.05 1976.5,3721.5 1976.5,3816 2007,3846.5 2007,3981.5 1986.5,4002 1986.5,4386.81 TFTLCD.1@1999.92,4400.24 ; v1(2493,1892) 2499.5,1892 2567.5,1960 2567.5,2011.12 2567.28,2011.12 U4.127@2567.28,2041.55
  Bottom Layer w10: v1(1142,1930) 1362,1710 1432,1710 1449,1693 1449,1624 1481,1592 1499.58,1592 P4.11@1499.58,1560.43 1771.21,1560.43 2028.28,1817.5 2418.5,1817.5 v1(2493,1892) ; v1(1179,3744) 1309,3744 1413,3640 1479,3640 1519,3680 v1(1991.95,3680)
FSMC_NOE: P4.18 TFTLCD.4 U3.41 U4.118 | length 4752.7
  Top Layer w10: P4.18@1399.58,1860.43 1444.15,1905 1625,1905 ; v1(1983.25,3473.25) 1873.25,3473.25 1804.5,3404.5 1804.5,3085 1795,3075.5 1795,2928 1677,2810 1677,1957 ; v1(2026,3516) 2067.54,3474.46 2108.54,3474.46 ; TFTLCD.4@2099.92,4500.24 2054.54,4454.86 2054.54,4345.61 2022.5,4313.57 2022.5,4042.49 2053.5,4011.49 2053.5,3920.5 2025.5,3892.5 2025.5,3839 1994.5,3808 1994.5,3739.5 2025.5,3708.5 2025.5,3557.5 2108.54,3474.46 ; v1(2145,2060) 2120.5,2035.5 2120.5,1716 2096,1691.5 2070.5,1691.5 1795.73,1966.27 1686.27,1966.27 1677,1957 ; U3.41@2167.91,3474.46 2108.54,3474.46 ; U4.118@2390.12,2041.55 2390.12,2072 2391,2072.88 2391,2114 v1(2392,2115) ; 1625,1905 1677,1957 ; 1625,1905 1677,1957
  Bottom Layer w10: v1(1983.25,3473.25) v1(2026,3516) ; v1(2145,2060) 2376,2060 2392,2076 v1(2392,2115)
FSMC_NWE: P4.17 TFTLCD.3 U3.17 U4.119 | length 4166.4
  Top Layer w10: v1(2300.8,1910) 2321.68,1910 2409.8,1998.13 U4.119@2409.8,2041.55 2409.8,2097 2424.03,2111.22 2424.03,2705.07 v1(2494.95,2776) ; v1(2486,4250) 2486,3977 2579.09,3883.91 2595.91,3883.91 ; v1(2574,3862) 2595.91,3883.91 ; 2595.91,3883.91 U3.17@2640.35,3883.91 2595.91,3883.91
  Bottom Layer w10: P4.17@1499.58,1860.43 1932.23,1860.43 1975.3,1903.5 2294.3,1903.5 v1(2300.8,1910) ; TFTLCD.3@2099.92,4400.24 2099.92,4302.58 2133,4269.5 2454.88,4269.5 2474.38,4250 v1(2486,4250) ; v1(2494.95,2776) 2488.45,2769.5 2384,2769.5 2361.5,2792 2361.5,2913.5 2463.5,3015.5 2463.5,3520.5 2420.45,3563.55 2420.45,3708.45 v1(2574,3862)
GBC_KEY: P3.16 U4.18 U7.2 | length 4502.4
  Top Layer w10: U4.18@3000.35,2474.62 3050.88,2474.62 v1(3065,2460.5) ; v1(3368,2320) 3418.02,2269.98 3418.02,1891.98 v1(3506.07,1803.93)
  Bottom Layer w10: v1(3065,2460.5) 3193.59,2460.5 3334.09,2320 v1(3368,2320) ; v1(3506.07,1803.93) 3666,1803.93 P3.16@4139.58,1800.43 4184,1756 4283,1756 4348,1821 4348,1881 4599,2132 4843.5,2132 5061.5,2350 5061.5,2456.5 5072,2467 5112,2467 5133,2446 5133,2164 5180,2117 6137.85,2117 U7.2@6240.43,2219.58
GBC_RX: P10.5 U7.3 | length 435.2
  Bottom Layer w10: P10.5@5880,2060 5940.53,1999.47 6008.16,1999.47 6026.18,2017.49 6138.34,2017.49 U7.3@6240.43,2119.58
GBC_TX: P10.6 U7.4 | length 503.6
  Top Layer w10: U7.4@6240.43,2019.58 6285,2064.15 6285,2143 v1(6258,2170)
  Bottom Layer w10: P10.6@5980,2060 6106.54,2060 6216.54,2170 v1(6258,2170)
